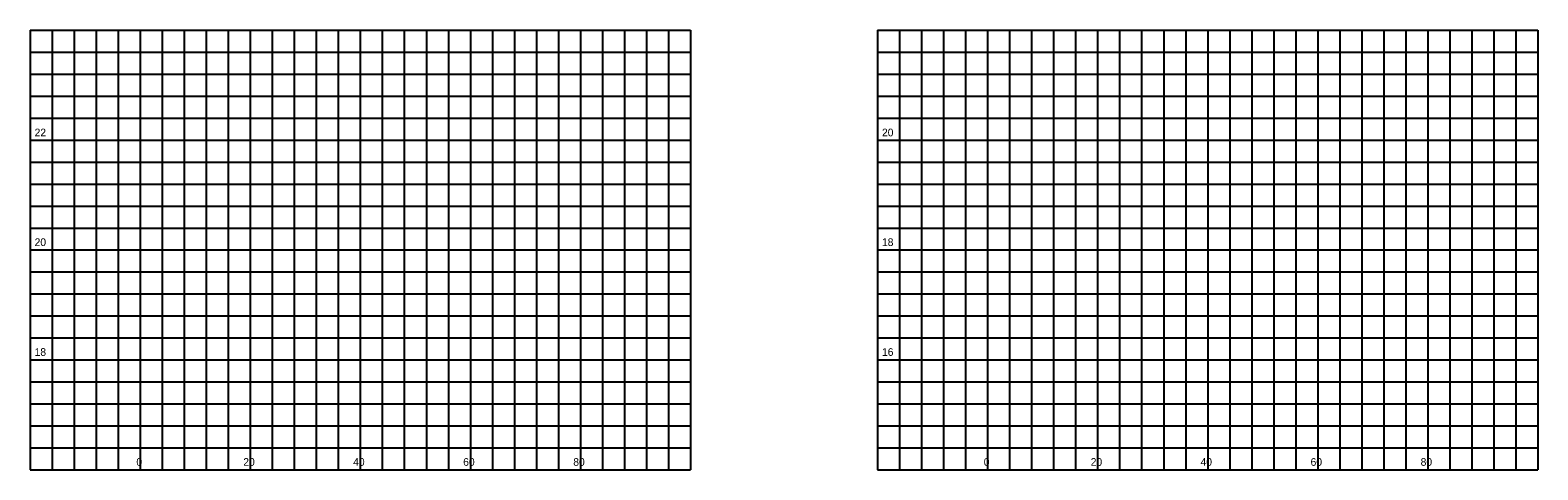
# Model space of a CAD drawing. Extents: x 127723 to 128378, y 21426 to 23736.
# Drawn here: x 128104.1 to 128378.1, y 23655.7 to 23735.7 of the extents above; entities that cross this region are included whole.
import ezdxf

# ---------------------------------------------------------------- set-up
doc = ezdxf.new("R2010")
doc.units = 0
for name, color, linetype in [('GroundCover', 7, 'Continuous'), ('Miscellaneous0', 7, 'Continuous'), ('SheetBorder_dp', 7, 'Continuous')]:
    doc.layers.add(name, color=color, linetype=linetype)

msp = doc.modelspace()

# ---------------------------------------------------------------- linework, layer by layer
at = {"layer": 'Miscellaneous0'}
for p, q in [((128108.11, 23735.67), (128108.11, 23655.67)), ((128112.11, 23735.67), (128112.11, 23655.67)), ((128116.11, 23735.67), (128116.11, 23655.67)), ((128120.11, 23735.67), (128120.11, 23655.67)), ((128128.11, 23735.67), (128128.11, 23655.67)), ((128132.11, 23735.67), (128132.11, 23655.67)), ((128136.11, 23735.67), (128136.11, 23655.67)), ((128140.11, 23735.67), (128140.11, 23655.67)), ((128148.11, 23735.67), (128148.11, 23655.67)), ((128152.11, 23735.67), (128152.11, 23655.67)), ((128156.11, 23735.67), (128156.11, 23655.67)), ((128160.11, 23735.67), (128160.11, 23655.67)), ((128168.11, 23735.67), (128168.11, 23655.67)), ((128172.11, 23735.67), (128172.11, 23655.67)), ((128176.11, 23735.67), (128176.11, 23655.67)), ((128180.11, 23735.67), (128180.11, 23655.67)), ((128188.11, 23735.67), (128188.11, 23655.67)), ((128192.11, 23735.67), (128192.11, 23655.67)), ((128196.11, 23735.67), (128196.11, 23655.67)), ((128200.11, 23735.67), (128200.11, 23655.67)), ((128208.11, 23735.67), (128208.11, 23655.67)), ((128212.11, 23735.67), (128212.11, 23655.67)), ((128216.11, 23735.67), (128216.11, 23655.67)), ((128220.11, 23735.67), (128220.11, 23655.67)), ((128262.11, 23735.67), (128262.11, 23655.67)), ((128266.11, 23735.67), (128266.11, 23655.67)), ((128270.11, 23735.67), (128270.11, 23655.67)), ((128274.11, 23735.67), (128274.11, 23655.67)), ((128282.11, 23735.67), (128282.11, 23655.67)), ((128286.11, 23735.67), (128286.11, 23655.67)), ((128290.11, 23735.67), (128290.11, 23655.67)), ((128294.11, 23735.67), (128294.11, 23655.67)), ((128302.11, 23735.67), (128302.11, 23655.67)), ((128306.11, 23735.67), (128306.11, 23655.67)), ((128310.11, 23735.67), (128310.11, 23655.67)), ((128314.11, 23735.67), (128314.11, 23655.67)), ((128322.11, 23735.67), (128322.11, 23655.67)), ((128326.11, 23735.67), (128326.11, 23655.67)), ((128330.11, 23735.67), (128330.11, 23655.67)), ((128334.11, 23735.67), (128334.11, 23655.67)), ((128342.11, 23735.67), (128342.11, 23655.67)), ((128346.11, 23735.67), (128346.11, 23655.67)), ((128350.11, 23735.67), (128350.11, 23655.67)), ((128354.11, 23735.67), (128354.11, 23655.67)), ((128362.11, 23735.67), (128362.11, 23655.67)), ((128366.11, 23735.67), (128366.11, 23655.67)), ((128370.11, 23735.67), (128370.11, 23655.67)), ((128374.11, 23735.67), (128374.11, 23655.67)), ((128104.11, 23731.67), (128224.11, 23731.67)), ((128258.11, 23731.67), (128378.11, 23731.67)), ((128104.11, 23727.67), (128224.11, 23727.67)), ((128258.11, 23727.67), (128378.11, 23727.67)), ((128104.11, 23723.67), (128224.11, 23723.67)), ((128258.11, 23723.67), (128378.11, 23723.67)), ((128104.11, 23719.67), (128224.11, 23719.67)), ((128258.11, 23719.67), (128378.11, 23719.67)), ((128104.11, 23711.67), (128224.11, 23711.67)), ((128258.11, 23711.67), (128378.11, 23711.67)), ((128104.11, 23707.67), (128224.11, 23707.67)), ((128258.11, 23707.67), (128378.11, 23707.67)), ((128104.11, 23703.67), (128224.11, 23703.67)), ((128258.11, 23703.67), (128378.11, 23703.67)), ((128104.11, 23699.67), (128224.11, 23699.67)), ((128258.11, 23699.67), (128378.11, 23699.67)), ((128104.11, 23691.67), (128224.11, 23691.67)), ((128258.11, 23691.67), (128378.11, 23691.67)), ((128104.11, 23687.67), (128224.11, 23687.67)), ((128258.11, 23687.67), (128378.11, 23687.67)), ((128104.11, 23683.67), (128224.11, 23683.67)), ((128258.11, 23683.67), (128378.11, 23683.67)), ((128104.11, 23679.67), (128224.11, 23679.67)), ((128258.11, 23679.67), (128378.11, 23679.67)), ((128104.11, 23671.67), (128224.11, 23671.67)), ((128258.11, 23671.67), (128378.11, 23671.67)), ((128104.11, 23667.67), (128224.11, 23667.67)), ((128258.11, 23667.67), (128378.11, 23667.67)), ((128104.11, 23663.67), (128224.11, 23663.67)), ((128258.11, 23663.67), (128378.11, 23663.67)), ((128104.11, 23659.67), (128224.11, 23659.67)), ((128258.11, 23659.67), (128378.11, 23659.67))]:
    msp.add_line(p, q, dxfattribs=at)
at = {"layer": 'SheetBorder_dp'}
for p, q in [((128104.11, 23735.67), (128224.11, 23735.67)), ((128104.11, 23735.67), (128104.11, 23655.67)), ((128124.11, 23735.67), (128124.11, 23675.67)), ((128124.11, 23735.67), (128124.11, 23655.67)), ((128144.11, 23735.67), (128144.11, 23655.67)), ((128164.11, 23735.67), (128164.11, 23655.67)), ((128184.11, 23735.67), (128184.11, 23655.67)), ((128204.11, 23735.67), (128204.11, 23655.67)), ((128224.11, 23735.67), (128224.11, 23655.67)), ((128258.11, 23735.67), (128378.11, 23735.67)), ((128258.11, 23735.67), (128258.11, 23655.67)), ((128278.11, 23735.67), (128278.11, 23675.67)), ((128278.11, 23735.67), (128278.11, 23655.67)), ((128298.11, 23735.67), (128298.11, 23655.67)), ((128318.11, 23735.67), (128318.11, 23655.67)), ((128338.11, 23735.67), (128338.11, 23655.67)), ((128358.11, 23735.67), (128358.11, 23655.67)), ((128378.11, 23735.67), (128378.11, 23655.67)), ((128104.11, 23715.67), (128224.11, 23715.67)), ((128258.11, 23715.67), (128378.11, 23715.67)), ((128104.11, 23695.67), (128224.11, 23695.67)), ((128258.11, 23695.67), (128378.11, 23695.67)), ((128104.11, 23675.67), (128184.11, 23675.67)), ((128104.11, 23675.67), (128224.11, 23675.67)), ((128258.11, 23675.67), (128338.11, 23675.67)), ((128258.11, 23675.67), (128378.11, 23675.67)), ((128104.11, 23655.67), (128224.11, 23655.67)), ((128258.11, 23655.67), (128378.11, 23655.67))]:
    msp.add_line(p, q, dxfattribs=at)

# ---------------------------------------------------------------- texts
at = {"layer": 'GroundCover'}
for s, p in [('22', (128104.92, 23716.35)), ('20', (128258.92, 23716.35)), ('20', (128104.92, 23696.39)), ('18', (128258.92, 23696.39)), ('18', (128104.92, 23676.41)), ('16', (128258.92, 23676.41)), ('0', (128123.41, 23656.41)), ('20', (128142.85, 23656.41)), ('40', (128162.81, 23656.41)), ('60', (128182.81, 23656.41)), ('80', (128202.81, 23656.41)), ('0', (128277.41, 23656.41)), ('20', (128296.85, 23656.41)), ('40', (128316.81, 23656.41)), ('60', (128336.81, 23656.41)), ('80', (128356.81, 23656.41))]:
    msp.add_text(s, height=1.4, dxfattribs=at).set_placement(p)

doc.saveas('drawing.dxf')
